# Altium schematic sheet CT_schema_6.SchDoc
size 304 x 256 mm
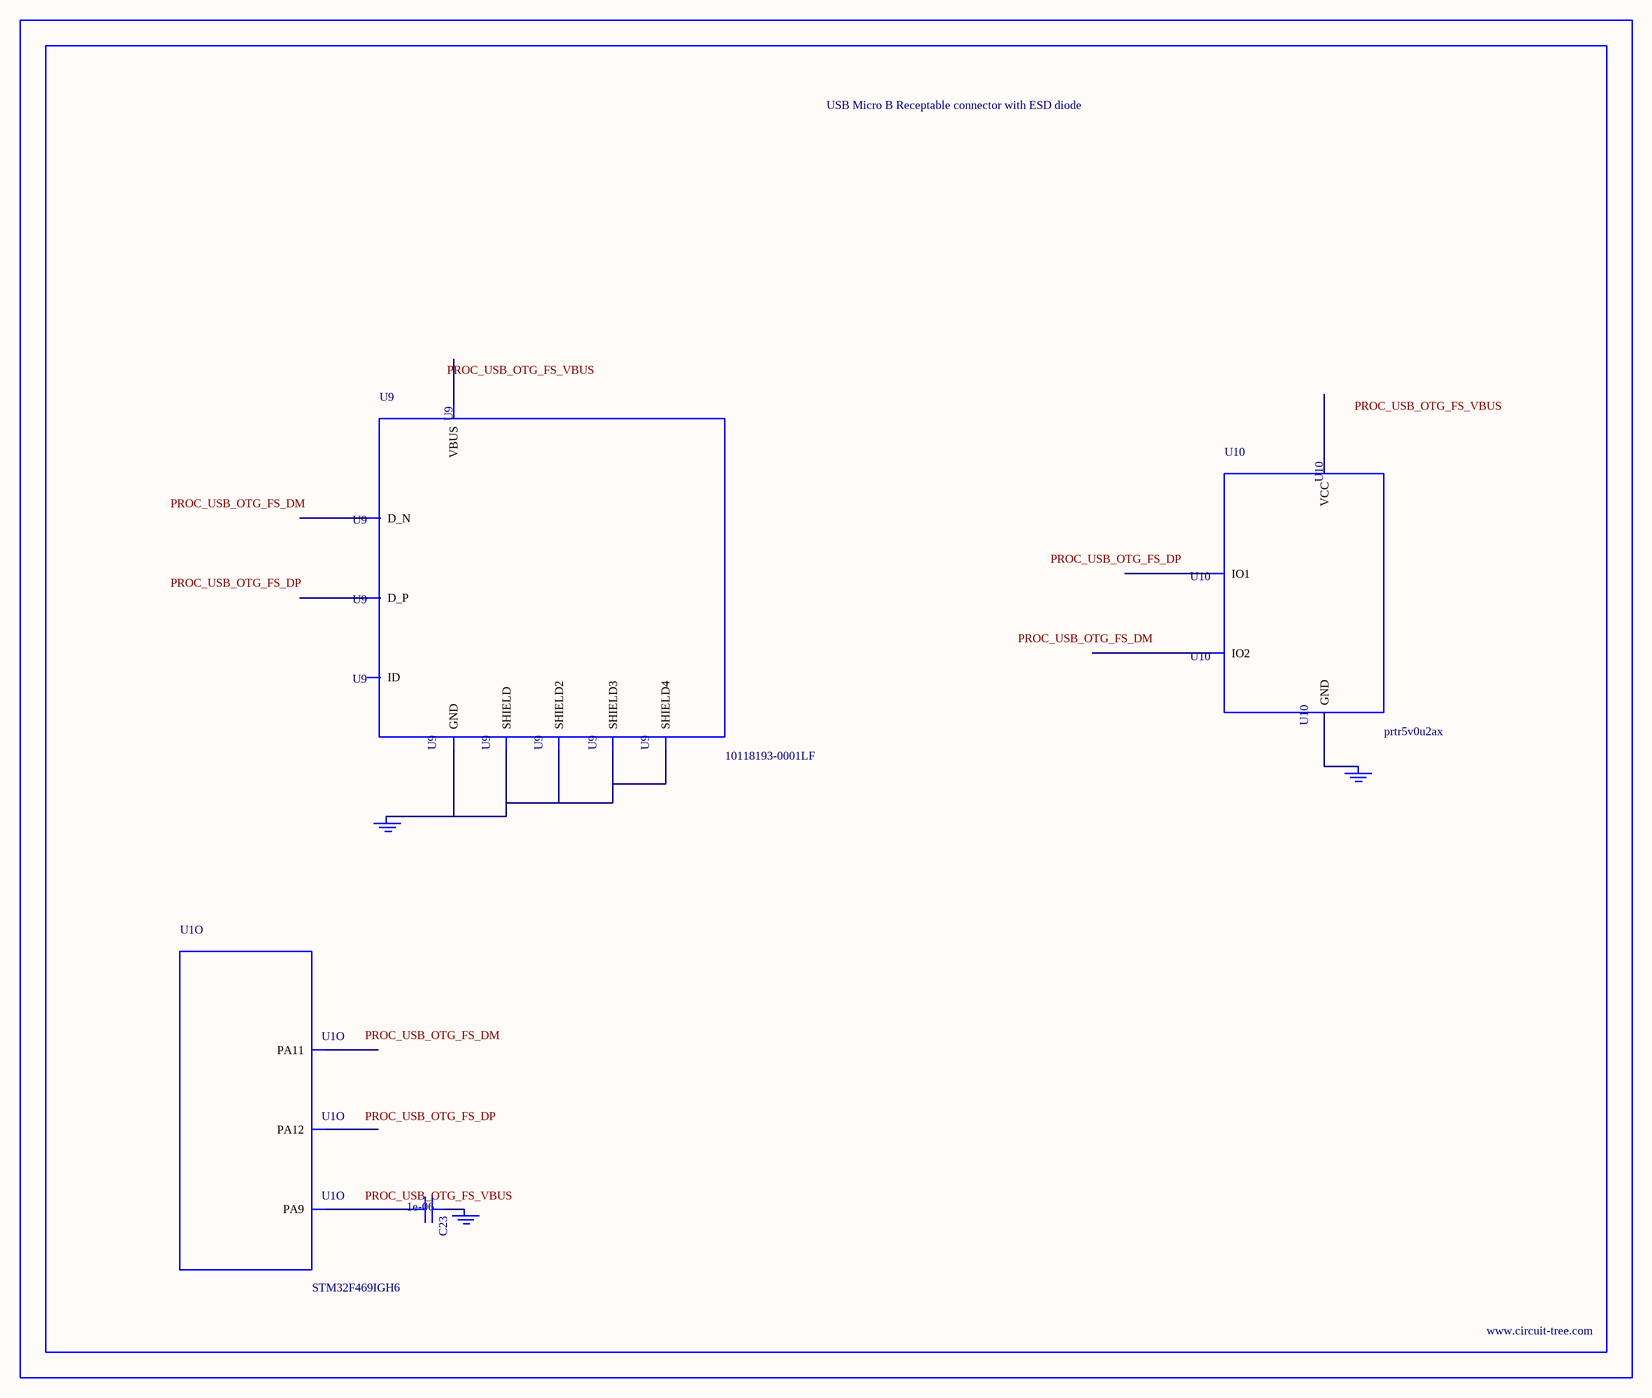
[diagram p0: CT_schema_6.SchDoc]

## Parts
BORDER5  (no value)
C23  1e-06  [C0603]
GND_INSTANCE_5_0  (no value)
GND_INSTANCE_5_1  (no value)
GND_INSTANCE_5_2  (no value)
U1  STM32F469IGH6  [UFBGA176]  (part O of 16)
U9  10118193-0001LF  [FCI_10118193-0001LF]
U10  prtr5v0u2ax  [SOT143B]

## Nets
NetC23_1: C23.1 GND_INSTANCE_5_1.0(GND)
NetC23_2: C23.2 U1.E15(PA9)
NetGND_INSTANCE_5_0_0: GND_INSTANCE_5_0.0(GND) U9.5(GND) U9.6(SHIELD) U9.7(SHIELD2) U9.8(SHIELD3) U9.9(SHIELD4)
NetGND_INSTANCE_5_2_0: GND_INSTANCE_5_2.0(GND) U10.1(GND)

Not connected (* = marked no-connect by the designer): U1 B15(PA12) C15(PA11); U9 1(VBUS) 2(D_N) 3(D_P) 4(ID); U10 2(IO1) 3(IO2) 4(VCC)

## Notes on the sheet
- Labels drawn without touching a wire or pin: PROC_USB_OTG_FS_DM, PROC_USB_OTG_FS_DP, PROC_USB_OTG_FS_VBUS

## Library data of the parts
BORDER5 = BORDER_PAGE5
C23 = C0603C105K3RACTU
GND_INSTANCE_5_0-GND_INSTANCE_5_2 = GND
